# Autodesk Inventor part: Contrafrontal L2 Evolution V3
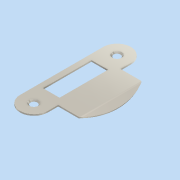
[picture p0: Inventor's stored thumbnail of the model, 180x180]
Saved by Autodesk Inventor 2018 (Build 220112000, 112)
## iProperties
Created: 2020-04
Part Number: Contrafrontal L2 Evolution V3
Material: Acero inoxidable
Document SubType Name: Modeling
Designer: PROYECTO
Density: 8 g/cm^3
Appearance: Titanio
Author: PROYECTO
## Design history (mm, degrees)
sketch "Boceto1"
  geometry: L1 (0, 0)-(0, 60); L2 (-10, 60)-(-10, 0); L3 (-6, 47.5)-(-6, 12.5); L4 (-6, 12.5)-(6, 12.5); L5 (6, 12.5)-(6, 47.5); L6 (6, 47.5)-(-6, 47.5); L7 (-6, 47.5)-(6, 12.5); L8 (-6, 12.5)-(6, 47.5); L9 (10, 52.5)-(25, 52.5); L10 (10, 7.5)-(25, 7.5); L11 (25, 52.5)-(25, 7.5); L12 (10, 0)-(10, 7.5); L13 (10, 52.5)-(10, 60); C1 r 2.5 at (0, 60); C2 r 2.5 at (0, 0); A1 r 10 centre (0, 0) between (-10, 0) and (10, 0); A2 r 10 centre (0, 60) between (10, 60) and (-10, 60); 1 further point
  constraints: 28 end point, 6 tangent, 4 centre point, 4 parallel, 4 point on circle, 3 horizontal, 3 midpoint, 2 coincident, 1 perpendicular, 1 vertical
  dimensions: "d1" = 12 distance of L5.end L3.start; "d2" = 35 distance of L4.end L5.end; "d3" = 60 distance of L1.start L1.end; "d4" = 5 diameter of C1; "d5" = 5 diameter of C2; "d7" = 45 distance between parallel lines of L10 L9; "d17" = 7.5 distance from line of L1.start L10; "d18" = 20 distance between parallel lines of L2 L13; "d19" = 35 distance between parallel lines of L2 L11
extrude "Extrusión1" new body sketch "Boceto1" distance "d11" = 1; taper "d12" = 0 deg
chamfer "Chaflán1" distance "d13" = 1; stored, may be unused: second distance "d14" = 2, angle "d15" = 45 deg
sketch "Boceto2"
  geometry: L1 (25, 52.5)-(25, 7.5) reference; A1 r 45 centre (-13.971, 30) between (25, 7.5) and (25, 52.5); 1 further point
  constraints: 2 point on circle, 1 centre point
  dimensions: "d20" = 45 radius of A1
extrude "Extrusión2" join sketch "Boceto2" distance "d21" = 1; taper "d22" = 0 deg
sketch "Boceto4"
  geometry: L1 (-25, 52.5)-(-25, 7.5); A1 r 45 centre (13.971, 30) between (-25, 52.5) and (-25, 7.5) reference; 1 further point
  constraints: 2 end point, 1 vertical
feature "Pieza de plegado1" sketch "Boceto4" dims "d23" = 2, "d24" = 25 deg
node "Sólido1"
other parameters: "d0" = 16
